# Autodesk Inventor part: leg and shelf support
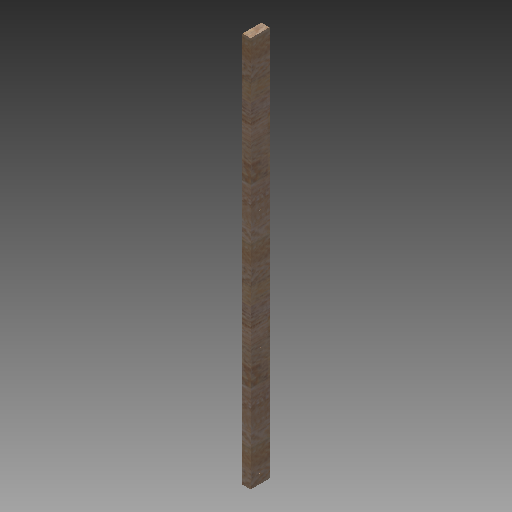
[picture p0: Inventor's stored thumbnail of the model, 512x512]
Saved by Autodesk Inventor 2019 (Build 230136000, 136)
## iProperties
Created: 2013-07
Part Number: leg and shelf support
Material: Generic
Document SubType Name: Modeling
Designer: Patrick Rice
Density: 1 g/cm^3
Appearance: Red Oak - Natural
Author: Patrick Rice
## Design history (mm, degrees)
sketch "Sketch1"
  geometry: L1 (0, 0)-(-38.1, 0); L2 (-38.1, 0)-(-38.1, 88.9); L3 (-38.1, 88.9)-(0, 88.9); L4 (0, 88.9)-(0, 0)
  constraints: 8 end point, 2 parallel, 1 horizontal, 1 perpendicular
  dimensions: "d0" = 38.1 distance of L2.end L3.end; "d1" = 88.9 distance of L1.end L2.end
extrude "Extrusion1" new body sketch "Sketch1" distance "d2" = 1828.8; taper "d3" = 0 deg
hole "Hole2" diameter "d15" = 6.35; stored, may be unused: countersink angle "d19" = 82 deg, drill point angle "d21" = 118 deg; dims "d13" = 44.45, "d14" = 717.55, "d16" = 19.05, "d17" = 19.05, "d18" = 12.7, "d20" = 25.4
hole "Hole3" diameter "d24" = 6.35; stored, may be unused: countersink angle "d28" = 82 deg, drill point angle "d30" = 118 deg; dims "d22" = 44.45, "d23" = 1276.35, "d25" = 19.05, "d26" = 19.05, "d27" = 12.7, "d29" = 25.4
hole "Hole4" diameter "d33" = 6.35; stored, may be unused: countersink angle "d37" = 82 deg, drill point angle "d39" = 118 deg; dims "d31" = 44.45, "d32" = 44.45, "d34" = 19.05, "d35" = 19.05, "d36" = 12.7, "d38" = 25.4
body "Solid1"
